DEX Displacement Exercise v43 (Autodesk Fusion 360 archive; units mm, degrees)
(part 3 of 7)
fillet "Fillet91" radius 4.5
extrude "Extrude128" sketch "Plate Cuts" profile of C3 C6 no distance stored from offset 0.5
extrude "Extrude129" sketch "Blister" profile of C8 C9 C11 C12 blind -4.5
mirror "Mirror7"
fillet "Fillet92" radius 1

design "RCT N17 Blister"
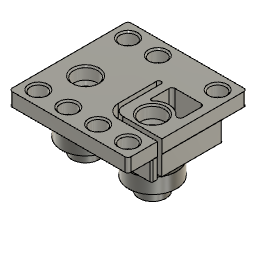
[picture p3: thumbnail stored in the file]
parameter "t_sheet_MAIN" = 6.6 comment "thickness of *most* of the gantry material"
parameter "t_sheet_SECOND" = 6.35 (= "1 / 4 * 1") comment "thickness of the webs"
parameter "od_bearings" = 16
parameter "id_bearings" = 5
parameter "t_bearings" = 5
parameter "p_belt" = 2
parameter "w_belt" = 10
parameter "t_belt" = 1.4
parameter "l_top_belt_to_rail" = 3
parameter "r_cutoutTool" = 2.05 (= "4.1 mm / 2")
parameter "hw_m3_thru" = 3.5
parameter "hw_m3_head" = 5.5
parameter "hw_m3_washer" = 7
parameter "hw_m3_thread" = 2.5
parameter "tab_breather" = 0.2 comment "tab clearance"
parameter "hw_m5_thread" = 4.2
parameter "hw_m5_head" = 8.5
parameter "hw_m5_washer" = 10
parameter "hw_m5_thru" = 5.25
parameter "hw_m6_thru" = 6.5
parameter "hw_m6_head" = 10
parameter "hw_m6_washer" = 12
parameter "l_beltblock" = 15
parameter "hw_plstf6_thread" = 2.94
parameter "hw_plstf6_thru" = 4
parameter "hw_plstf6_head" = 6.86
parameter "hw_plstf6_washer" = 7.92
parameter "hw_m3_flathead" = 6
parameter "hw_m4insert_d" = 6
parameter "hw_m4insert_l" = 4.8
parameter "hw_m4_tappedwj" = 3.3
parameter "hw_m4_thru" = 4.25
parameter "hw_m4_head" = 7
parameter "hw_m4_headheight" = 4
parameter "preload_bearings" = 0.55
parameter "hw_m3insert_d" = 5.4
parameter "hw_m3insert_l" = 3.8
parameter "dist_clearance" = 0.5
parameter "hw_shoulder_headDiameter" = 9
parameter "hw_shoulder_headHeight" = 4
parameter "l_travel" = 405 comment "will be rounded to 10s"
parameter "User Parameter" = 0 (= "min 10")
parameter "nh_rail_width" = "nh_gantry_width - 3"
parameter "l_shoulder_thread" = 10
parameter "hw_n6_thru" = 4.064
parameter "hw_n6_thread" = 3.1
parameter "hw_n6_flathead" = 6.6548
parameter "hw_n6_head" = 6.858
parameter "carriage_offsets" = 0.25
parameter "hw_momentPin_reald" = 3.683
parameter "pinch_by" = 0.2
parameter "d285" = 2
parameter "d344" = 3.5
parameter "d482" = 3.3 (= "t_sheet_MAIN / 2")
parameter "d578" = 0.5
parameter "d683" = 3.683 (= "hw_momentPin_reald")
parameter "d689" = 0.5
parameter "d698" = 5
parameter "d705" = 3.5415 (= "d683 / 2 + 1.7 mm")
parameter "d837" = 0.25
sketch "Plate Cuts" plane through (0, 0, 0) normal (0, 0, 1) x axis (1, 0, 0)
  line L1 (0, 60) -> (0, 0)
  line L2 (3.3, 0) -> (3.3, 60)
  line L3 (-3.3, 60) -> (-3.3, 0)
  line L4 (-15, 10) -> (-5, 10)
  line L5 (-15, 40) -> (-5, 40)
  line L6 (15, 10) -> (5, 10)
  line L7 (-20, 37) -> (-20, 13)
  line L8 (-2, 37) -> (-20, 37)
  line L9 (-2, 43) -> (-2, 37)
  line L10 (12, 43) -> (-2, 43)
  line L11 (12, 37) -> (12, 43)
  line L12 (20.5, 37) -> (12, 37)
  line L13 (20.5, 13) -> (20.5, 37)
  line L14 (-20, 13) -> (20.5, 13)
  circle C1 centre (-5, 10) radius 1.575
  circle C2 centre (-15, 10) radius 1.575
  circle C3 centre (-11.2, 22) radius 8
  circle C4 centre (-15, 40) radius 1.575
  circle C5 centre (-5, 40) radius 1.575
  circle C6 centre (11.2, 22) radius 8
  circle C7 centre (15, 40) radius 1.575
  circle C8 centre (5, 10) radius 1.575
  circle C9 centre (15, 10) radius 1.575
  circle C10 centre (-11.2, 22) radius 8.25
  circle C11 centre (11.2, 22) radius 8.25
  point P1 (0, 0)
  point P2 (0, 0)
  point P3 (0, 60)
  point P7 (-3.3, 60)
  point P4 (3.3, 60)
  point P6 (-3.3, 0)
  point P5 (3.3, 0)
  point P8 (-5, 10)
  point P10 (-5, 10)
  point P9 (-15, 10)
  point P11 (-15, 10)
  point P14 (-15, 40)
  point P15 (-15, 40)
  point P13 (-5, 40)
  point P16 (-5, 40)
  point P12 (-11.2, 22)
  point P17 (11.2, 22)
  point P18 (15, 40)
  point P19 (5, 10)
  point P21 (5, 10)
  point P20 (15, 10)
  point P22 (15, 10)
  point P27 (-2, 37)
  point P25 (-20, 13)
  point P33 (-20, 13)
  coincident P1 P2
  vertical L1
  parallel L1 L2
  parallel L1 L3
  horizontal P3 P7
  horizontal P3 P4
  horizontal P1 P6
  horizontal P1 P5
  coincident P8 P10
  horizontal L4
  coincident P9 P11
  equal C1 C2
  horizontal L5
  coincident P14 P15
  coincident P13 P16
  equal L4 L5
  equal C2 C4
  equal C1 C5
  equal C3 C6
  horizontal P12 P17
  equal C5 C7
  horizontal P16 P18
  horizontal L6
  coincident P19 P21
  coincident P20 P22
  equal C2 C8
  equal C2 C9
  equal L4 L6
  concentric C3 C10
  concentric C6 C11
  vertical L7
  perpendicular L3 L8
  perpendicular L8 L9
  perpendicular L9 L10
  perpendicular L8 L11
  perpendicular L11 L12
  perpendicular L12 L13
  coincident P27 L12
  perpendicular L13 L14
  coincident P25 P33
  dimension "d1151" distance P2 P3 = 60
  dimension "d1152" distance L1 L3 = 3.3 (= "t_sheet_MAIN / 2")
  dimension "d1153" distance L1 L2 = 3.3 (= "d1152")
  dimension "d1154" distance L1 P8 = 5
  dimension "d1156" distance P10 P11 = 10
  dimension "d1157" diameter C2 = 3.15
  dimension "d1158" distance P1 L4 = 10
  dimension "d1159" diameter C3 = 16 (= "od_bearings")
  dimension "d1160" distance P9 L5 = 30
  dimension "d1161" distance L1 P16 = 5
  dimension "d1162" distance L1 P12 = 11.2 (= "od_bearings / 2 + t_sheet_MAIN / 2 - pinch_by / 2")
  dimension "d1163" distance P9 P12 = 12
  dimension "d1164" distance L1 P17 = 11.2 (= "d1162")
  dimension "d1165" distance P16 P18 = 20
  dimension "d1166" distance P1 L6 = 10
  dimension "d1167" distance L1 P21 = 5
  dimension "d1168" distance C6 C11 = 0.25
  dimension "d1169" distance C3 C10 = 0.25 (= "d1168")
  dimension "d1171" distance P16 L9 = 3
  dimension "d1172" distance P16 L8 = 3
  dimension "d1174" distance P16 L10 = 3
  dimension "d1175" distance P18 L11 = 3
  dimension "d1176" distance P18 L13 = 5.5
  dimension "d1177" distance P21 L14 = 3
  dimension "d1229" distance P15 L7 = 5
  dimension "d996" distance = 1.2
  dimension "d997" distance = 5
  dimension "d998" diameter = 24
  dimension "d999" distance = 15
  dimension "d1000" ProfileOffset = 2
  dimension "d1001" AlongDistance = 10
  dimension "d1002" TaperAngle = 0
  dimension "d1004" TaperAngle = 0
  dimension "d1005" ProfileOffset = -0.5
  dimension "d1006" AlongDistance = -55
  dimension "d1007" TaperAngle = 0
  dimension "d467" angle = 5
  dimension "d469" angle = 5
  dimension "d470" angle = 5
  dimension "d471" diameter = 3.5 (= "hw_m3_thru")
  dimension "d472" diameter = 7 (= "hw_m3_washer")
  dimension "d475" distance = 2.4 (= "t_belt + 1 mm")
  dimension "d476" distance = 2.4 (= "d475")
  dimension "d477" distance = 4.477
  dimension "d479" distance = 1
  dimension "d480" distance = 0.75
  dimension "d485" distance = 0.75 (= "d480")
  dimension "d487" diameter = 3.1 (= "hw_n6_thread")
  dimension "d488" diameter = 4.064 (= "hw_n6_thru")
  dimension "d489" Side1Offset = 0.5
  dimension "d490" TaperAngle = 0
  dimension "d491" Side1Offset = 0
  dimension "d492" TaperAngle = 0
  dimension "d493" Side1Offset = 0
  dimension "d494" TaperAngle = 0
  dimension "d495" Side1Offset = 1
  dimension "d496" TaperAngle = 0
  dimension "d497" distance = 9
  dimension "d498" angle = 5 (= "d469")
  dimension "d500" distance = 5
  dimension "d501" radius = 11.075 (= "( 22.15 / 2 ) * 1 mm")
  dimension "d502" Side1Offset = 0
  dimension "d503" TaperAngle = 0
  dimension "d504" diameter = 5.3 (= "hw_m3insert_d - 0.1 mm")
  dimension "d506" diameter = 3.5 (= "hw_m3_thru")
  dimension "d507" Side1Offset = 0
  dimension "d508" TaperAngle = 0
  dimension "d509" AlongDistance = -5
  dimension "d510" TaperAngle = 0
  dimension "d529" AlongDistance = 100
  dimension "d530" TaperAngle = 0
  dimension "d531" countU = 13 (= "nh_gantry_length + 1")
  dimension "d532" CountV = 9 (= "nh_gantry_width + 1")
  dimension "d533" uSpaceDistance = 10
  dimension "d534" vSpaceDistance = -10
  dimension "d535" diameter = 3.3 (= "hw_m4_tappedwj")
  dimension "d541" uSpaceDistance = 10
  dimension "d542" vSpaceDistance = 10
  dimension "d560" distance = 6.6 (= "t_sheet_MAIN")
  dimension "d563" distance = 5 (= "t_bearings")
  dimension "d564" distance = 16 (= "od_bearings")
  dimension "d565" angle = 45 (= "d566")
  dimension "d566" angle = 45
  dimension "d567" distance = 10 (= "l_shoulder_thread")
  dimension "d568" distance = 6.6 (= "t_sheet_MAIN")
  dimension "d569" distance = 45 (= "( ( nh_gantry_width * 10 ) * 1 mm + 10 mm ) / 2")
  dimension "d571" distance = 4.5 (= "hw_shoulder_headHeight + 0.5 mm")
  dimension "d572" distance = 4.5 (= "hw_shoulder_headDiameter / 2")
  dimension "d574" distance = 8.8037
  dimension "d576" distance = 0.5
  dimension "d577" distance = 0.5
  dimension "d580" distance = 0.5
  dimension "d581" distance = 3.5 (= "hw_m4insert_d / 2 + 0.5 mm")
  dimension "d582" distance = 3.5 (= "d581")
  dimension "d583" distance = 2.1
  dimension "d584" distance = 0.8383
  dimension "d586" distance = 1.269 (= "0.5 mm + 0.769 mm")
  dimension "d587" distance = 5
  dimension "d588" distance = 10
  dimension "d589" distance = 5
  dimension "d590" AlongDistance = 65 (= "( nh_gantry_length * 10 + 10 ) / 2 * 1 mm")
  dimension "d591" TaperAngle = 0
  dimension "d597" ProfileOffset = 0.25 (= "carriage_offsets")
  dimension "d599" TaperAngle = 0
  dimension "d601" diameter = 16 (= "od_bearings")
  dimension "d602" diameter = 6 (= "hw_m4insert_d")
  dimension "d603" diameter = 4
  dimension "d604" distance = 0.25
  dimension "d606" AlongDistance = -20
  dimension "d607" TaperAngle = 0
  dimension "d608" ProfileOffset = 0.5
  dimension "d609" AlongDistance = 5 (= "t_bearings")
  dimension "d610" TaperAngle = 0
  dimension "d612" distance = 0.25
  dimension "d613" diameter = 4
  dimension "d614" diameter = 6 (= "hw_m4insert_d")
  dimension "d615" diameter = 16 (= "od_bearings")
  dimension "d616" AlongDistance = -20
  dimension "d617" TaperAngle = 0
  dimension "d618" ProfileOffset = 0.5
  dimension "d619" AlongDistance = 5 (= "t_bearings")
  dimension "d620" TaperAngle = 0
  dimension "d621" AlongDistance = 670 (= "l_actual_complete")
  dimension "d622" TaperAngle = 0
  dimension "d623" distance = 0.1
  dimension "d624" distance = 1.6455
  dimension "d625" distance = 3.4128
  dimension "d626" distance = 13.2 (= "0.5 in + 0.5 mm")
  dimension "d628" distance = 5
  dimension "d630" distance = 30
  dimension "d631" diameter = 4.064 (= "hw_n6_thru")
  dimension "d636" diameter = 6.6548 (= "hw_n6_flathead")
  dimension "d637" diameter = 3.1 (= "hw_n6_thread")
  dimension "d638" distance = 4
  dimension "d639" distance = 4 (= "d638")
  dimension "d641" TaperAngle = 0
  dimension "d642" ProfileOffset = 0
  dimension "d643" Side1Offset = 0
  dimension "d644" TaperAngle = 0
  dimension "d645" ProfileOffset = 0
  dimension "d646" Side1Offset = 0
  dimension "d647" TaperAngle = 0
  dimension "d648" distance = 5
  dimension "d649" distance = 0.75
  dimension "d650" ProfileOffset = 0
  dimension "d651" Side1Offset = 0
  dimension "d652" TaperAngle = 0
  dimension "d653" AlongDistance = 21
  dimension "d654" TaperAngle = 0
  dimension "d655" distance = 1
  dimension "d656" ProfileOffset = 0
  dimension "d657" Side1Offset = 0
  dimension "d658" TaperAngle = 0
  dimension "d659" AlongDistance = 12
  dimension "d660" TaperAngle = 0
  dimension "d661" Side1Offset = 0
  dimension "d662" TaperAngle = 0
  dimension "d667" Radius = 4
  dimension "d669" Radius = 4
  dimension "d670" Radius = 1
  dimension "d673" Radius = 0.5
  dimension "d674" Radius = 0.5
  dimension "d675" Radius = 0.5
  dimension "d676" Radius = 0.5
  dimension "d677" Radius = 0.2
  dimension "d680" distance = 40
  dimension "d681" distance = 6
  dimension "d691" distance = 2.54
  dimension "d692" distance = 0.5 (= "d689")
  dimension "d693" distance = 0.5
  dimension "d696" distance = 0.5
  dimension "d697" distance = 5
  dimension "d701" distance = 1.7
  dimension "d702" distance = 1.7 (= "d701")
  dimension "d706" distance = 2.54 (= "d691")
  dimension "d707" distance = 3.5
  dimension "d708" distance = 0.5
  dimension "d709" ProfileOffset = 0
  dimension "d710" Side1Offset = 0
  dimension "d711" TaperAngle = 0
  dimension "d712" ProfileOffset = 0
  dimension "d713" Side1Offset = 5
  dimension "d714" TaperAngle = 0
  dimension "d715" Side1Offset = 0
  dimension "d716" TaperAngle = 0
  dimension "d717" distance = 0.75
  dimension "d718" distance = 1.7
  dimension "d719" diameter = 16 (= "od_bearings")
  dimension "d720" diameter = 6 (= "hw_m4insert_d")
  dimension "d721" diameter = 4
  dimension "d722" distance = 0.25
  dimension "d723" AlongDistance = -19
  dimension "d724" TaperAngle = 0
  dimension "d725" distance = 1
  dimension "d726" ProfileOffset = 0.5
  dimension "d727" AlongDistance = 5 (= "t_bearings")
  dimension "d728" TaperAngle = 0
  dimension "d729" diameter = 4
  dimension "d730" diameter = 6 (= "hw_m4insert_d")
  dimension "d731" diameter = 16 (= "od_bearings")
  dimension "d732" distance = 1
  dimension "d733" distance = 0.25
  dimension "d734" AlongDistance = -26
  dimension "d735" TaperAngle = 0
  dimension "d736" ProfileOffset = 0.5
  dimension "d737" AlongDistance = 5 (= "t_bearings")
  dimension "d738" TaperAngle = 0
  dimension "d739" distance = 6
  dimension "d740" ProfileOffset = 0
  dimension "d741" Side1Offset = 0
  dimension "d742" TaperAngle = 0
  dimension "d743" Radius = 4
  dimension "d744" distance = -1
  dimension "d745" AlongDistance = 32
  dimension "d746" TaperAngle = 0
  dimension "d747" distance = 0.5
  dimension "d748" distance = 1
  dimension "d749" ProfileOffset = 0
  dimension "d750" AlongDistance = 3
  dimension "d751" TaperAngle = 0
  dimension "d752" ProfileOffset = 0
  dimension "d753" Side1Offset = 0
  dimension "d754" TaperAngle = 0
  dimension "d755" Side1Offset = 0
  dimension "d756" TaperAngle = 0
  dimension "d757" ProfileOffset = 0
  dimension "d758" Side1Offset = 0
  dimension "d759" TaperAngle = 0
  dimension "d760" AlongDistance = 12
  dimension "d761" TaperAngle = 0
  dimension "d762" AlongDistance = -37
  dimension "d763" TaperAngle = 0
  dimension "d764" Side1Offset = 0.5
  dimension "d765" TaperAngle = 0
  dimension "d767" Radius = 3
  dimension "d768" Radius = 2
  dimension "d770" Radius = 3
  dimension "d771" Radius = 3
  dimension "d772" distance = 3
  dimension "d773" distance = 3
  dimension "d774" Radius = 1
  dimension "d775" Radius = 0.5
  dimension "d776" Radius = 2
  dimension "d777" diameter = 5.4 (= "hw_m3insert_d")
  dimension "d778" diameter = 3.5 (= "hw_m3_thru")
  dimension "d779" Side1Offset = 0
  dimension "d780" TaperAngle = 0
  dimension "d781" Side1Offset = 0
  dimension "d782" TaperAngle = 0
  dimension "d783" Radius = 2
  dimension "d784" Radius = 2
  dimension "d785" Radius = 2
  dimension "d786" Radius = 3
  dimension "d788" Radius = 0.5
  dimension "d789" distance = 12
  dimension "d790" distance = 2
  dimension "d791" angle = 45
  dimension "d793" Radius = 2
  dimension "d794" Radius = 2
  dimension "d795" Radius = 1
  dimension "d797" Radius = 2
  dimension "d798" Radius = 1
  dimension "d799" Radius = 2
  dimension "d800" Radius = 4.5
  dimension "d801" distance = 0.275 (= "preload_bearings / 2")
  dimension "d803" distance = -0.5
  dimension "d806" distance = 3
  dimension "d807" AlongDistance = -60
  dimension "d808" distance = 3.8274 (= "d430 / 2")
  dimension "d809" distance = 0.423 (= "1 mm - 0.577 mm")
  dimension "d810" distance = 0.5
  dimension "d813" Side1Offset = 0
  dimension "d814" TaperAngle = 0
  dimension "d815" distance = 0.1
  dimension "d816" distance = 1.75
  dimension "d818" distance = 35
  dimension "d820" distance = 5
  dimension "d821" distance = 5
  dimension "d822" diameter = 4.064 (= "hw_n6_thru")
  dimension "d823" diameter = 6.6548 (= "hw_n6_flathead")
  dimension "d824" distance = 0.6
  dimension "d825" distance = 0.6 (= "d824")
  dimension "d827" TaperAngle = 0
  dimension "d828" diameter = 3.1 (= "hw_n6_thread")
  dimension "d829" Side1Offset = 0
  dimension "d830" TaperAngle = 0
  dimension "d831" distance = 4
  dimension "d832" distance = 4.477 (= "d833")
  dimension "d833" distance = 4.477 (= "d477")
  dimension "d836" diameter = 6.6548 (= "hw_n6_flathead")
  dimension "d839" Side1Offset = 0
  dimension "d840" TaperAngle = 0
  dimension "d841" distance = 0.9
  dimension "d842" angle = 50
  dimension "d843" angle = 50
  dimension "d844" distance = 8
  dimension "d845" distance = 5
  dimension "d846" diameter = 4.5
  dimension "d847" AlongDistance = -7
  dimension "d848" TaperAngle = 0
  dimension "d849" leftDistance = 0.75
  dimension "d850" ProfileOffset = 0
  dimension "d851" Side1Offset = 0
  dimension "d852" TaperAngle = 0
  dimension "d853" ProfileOffset = 0
  dimension "d854" Side1Offset = 0
  dimension "d855" TaperAngle = 0
  dimension "d856" distance = 12.7
  dimension "d857" leftDistance = 1.5
  dimension "d858" distance = 1.5454
  dimension "d859" Radius = 4
  dimension "d860" Radius = 2
  dimension "d861" Radius = 2
  dimension "d862" Radius = 4
  dimension "d863" Radius = 2
  dimension "d864" Radius = 35
  dimension "d865" Radius = 4
  dimension "d866" Radius = 1
  dimension "d869" Side1Offset = 0
  dimension "d870" TaperAngle = 0
  dimension "d872" distance = 1.5
  dimension "d873" leftDistance = 1.5
  dimension "d874" Radius = 2
  dimension "d885" distance = 27.775
  dimension "d886" distance = 30.275 (= "30 mm + preload_bearings / 2")
  dimension "d889" diameter = 3.3 (= "hw_m4_tappedwj")
  dimension "d890" distance = 5
  dimension "d891" distance = 10.275 (= "10 mm + preload_bearings / 2")
  dimension "d893" TaperAngle = 0
  dimension "d894" distance = 17.5
  dimension "d895" distance = 27.5
  dimension "d896" distance = 0.2
  dimension "d897" distance = 0.2 (= "d896")
  dimension "d900" distance = 6
  dimension "d902" distance = 3.7 (= "2 mm + 1.2 mm + 0.5 mm")
  dimension "d903" distance = 1
  dimension "d904" distance = 8
  dimension "d905" distance = 2.54
  dimension "d906" distance = 2.54
  dimension "d907" distance = 2.54
  dimension "d908" Side1Offset = 0
  dimension "d909" TaperAngle = 0
  dimension "d910" ProfileOffset = 0
  dimension "d911" Side1Offset = 0
  dimension "d912" TaperAngle = 0
  dimension "d913" leftDistance = 1.5
  dimension "d915" distance = 5.65
  dimension "d916" distance = 14.65
  dimension "d917" distance = 14.65
  dimension "d918" Side1Offset = 0
  dimension "d919" TaperAngle = 0
  dimension "d920" ChordLen = 4
  dimension "d921" ChordLen = 1
  dimension "d923" distance = 2.54
  dimension "d924" Radius = 2
sketch "Blister" plane through (0, 0, 0) normal (0, 0, 1) x axis (1, 0, 0)
  line L1 (-19.9, 44.9) -> (-19.9, 5.1)
  line L2 (19.9, 44.9) -> (-19.9, 44.9)
  line L3 (19.9, 5.1) -> (19.9, 44.9)
  line L4 (-19.9, 5.1) -> (19.9, 5.1)
  line L5 (3.8, 16.46) -> (3.8, 44.9)
  line L6 (3.3, 0) -> (3.3, 60)
  line L7 (7.44, 33.2818) -> (16.26, 33.2818)
  line L8 (6.44, 26.2818) -> (6.44, 32.2818)
  line L9 (17.26, 32.2818) -> (17.26, 26.2818)
  line L10 (19.9, 16.46) -> (3.8, 16.46)
  line L11 (2.3, 14.96) -> (19.9, 14.96)
  line L12 (2.3, 32.2818) -> (2.3, 14.96)
  line L13 (-1.9, 36.9) -> (-1.9, 42.9)
  line L14 (-19.9, 36.9) -> (-1.9, 36.9)
  line L15 (19.9, 13.1) -> (-19.9, 13.1)
  line L16 (11.9, 42.9) -> (-1.9, 42.9)
  line L17 (11.9, 36.9) -> (11.9, 42.9)
  line L18 (19.9, 36.9) -> (11.9, 36.9)
  line L19 (-3.55, 19.6596) -> (-3.55, 24.3404)
  line L20 (-3.3, 60) -> (-3.3, 0)
  line L21 (19.8, 36.9) -> (19.8, 13.1)
  line L22 (-19.8, 13.1) -> (-19.8, 36.9)
  circle C1 centre (-15, 10) radius 2.7
  circle C2 centre (-5, 10) radius 2.7
  circle C3 centre (5, 10) radius 2.7
  circle C4 centre (15, 10) radius 2.7
  circle C5 centre (15, 40) radius 2.7
  circle C6 centre (-5, 40) radius 2.7
  circle C7 centre (-15, 40) radius 2.7
  circle C8 centre (11.2, 22) radius 4.5
  circle C9 centre (11.2, 22) radius 3
  circle C10 centre (11.2, 22) radius 5.54
  arc A1 centre (6.94, 26.2818) radius 0.5 clockwise from (7.2926, 25.9274) to (6.44, 26.2818)
  arc A2 centre (16.2097, 26.2818) radius 1.0503 clockwise from (17.26, 26.2818) to (15.4114, 25.5994)
  arc A3 centre (7.44, 32.2818) radius 1 clockwise from (6.44, 32.2818) to (7.44, 33.2818)
  arc A4 centre (16.26, 32.2818) radius 1 clockwise from (16.26, 33.2818) to (17.26, 32.2818)
  arc A5 centre (3.05, 32.2818) radius 0.75 clockwise from (2.3, 32.2818) to (3.8, 32.2818)
  circle C11 centre (-11.2, 22) radius 3
  circle C12 centre (-11.2, 22) radius 4.5
  circle C13 centre (-11.2, 22) radius 8
  circle C14 centre (11.2, 22) radius 4
  circle C15 centre (-11.2, 22) radius 4
  point P6 (-15, 10)
  point P8 (-15, 10)
  point P14 (-15, 40)
  point P15 (-15, 40)
  point P13 (-5, 40)
  point P16 (-5, 40)
  point P7 (15, 40)
  point P12 (15, 40)
  point P11 (15, 10)
  point P17 (15, 10)
  point P10 (5, 10)
  point P18 (5, 10)
  point P9 (-5, 10)
  point P19 (-5, 10)
  point P20 (11.2, 22)
  point P21 (11.2, 22)
  point P22 (11.2, 22)
  point P23 (3.8, 44.9)
  point P34 (19.9, 16.46)
  point P35 (7.2926, 25.9274)
  point P30 (6.44, 26.2818)
  point P31 (17.26, 26.2818)
  point P37 (15.4114, 25.5994)
  point P27 (16.26, 33.2818)
  point P40 (16.26, 33.2818)
  point P42 (19.9, 14.96)
  point P45 (3.8, 32.2818)
  point P29 (6.44, 32.2818)
  point P47 (-11.2, 22)
  point P48 (-11.2, 22)
  point P49 (-11.2, 22)
  point P50 (-11.2, 22)
  point P55 (19.9, 13.1)
  point P58 (19.9, 36.9)
  point P52 (-1.9, 36.9)
  point P59 (-3.55, 24.3404)
  point P60 (-3.55, 19.6596)
  point P54 (-19.9, 13.1)
  point P53 (-19.9, 36.9)
  point P63 (19.8, 13.1)
  point P64 (19.8, 36.9)
  point P65 (-19.8, 36.9)
  point P66 (-19.8, 13.1)
  vertical L1
  perpendicular L1 L2
  perpendicular L2 L3
  perpendicular L3 L4
  coincident P6 P8
  equal C1 C7
  equal C1 C2
  equal C1 C3
  equal C1 C4
  equal C1 C6
  equal C1 C5
  coincident P14 P15
  coincident P13 P16
  coincident P7 P12
  coincident P11 P17
  coincident P10 P18
  coincident P9 P19
  coincident P20 P21
  coincident P21 P22
  parallel L3 L5
  coincident L2 P23
  perpendicular L3 L7
  vertical L8
  vertical L9
  concentric C9 C10
  coincident L3 P34
  perpendicular L3 L10
  tangent C10 L10
  tangent L8 A1
  coincident C10 P35
  tangent C10 A1
  horizontal P30 P31
  tangent L9 A2
  coincident C10 P37
  tangent C10 A2
  tangent L8 A3
  tangent L7 A4
  coincident P27 P40
  tangent L9 A4
  tangent L7 A3
  coincident L3 P42
  perpendicular L6 L11
  perpendicular L11 L12
  tangent L5 A5
  tangent L12 A5
  coincident L5 P45
  horizontal P29 P45
  coincident P47 P48
  coincident P47 P49
  coincident P47 P50
  perpendicular L13 L14
  perpendicular L3 L15
  coincident L3 P55
  horizontal L14
  perpendicular L13 L16
  perpendicular L2 L17
  coincident L3 P58
  perpendicular L3 L18
  coincident P52 L18
  coincident C13 P59
  coincident C13 P60
  vertical L19
  coincident L1 P54
  coincident L1 P53
  coincident L15 P63
  coincident L18 P64
  perpendicular L18 L21
  coincident L14 P65
  coincident L15 P66
  perpendicular L15 L22
  concentric C9 C14
  concentric C13 C15
  dimension "d1178" distance L4 P6 = 4.9
  dimension "d1179" distance L1 P6 = 4.9
  dimension "d1180" distance L2 P7 = 4.9
  dimension "d1181" distance L3 P7 = 4.9 (= "d1180")
  dimension "d1182" diameter C1 = 5.4 (= "hw_m3insert_d")
  dimension "d1183" diameter C8 = 9
  dimension "d1184" diameter C9 = 6 (= "hw_m4insert_d")
  dimension "d1185" distance L5 L6 = 0.5
  dimension "d1186" distance L3 L9 = 2.64
  dimension "d1187" distance L5 L8 = 2.64 (= "d1186")
  dimension "d1188" distance P29 P30 = 6
  dimension "d1189" distance C9 C10 = 2.54
  dimension "d1190" radius A1 = 0.5
  dimension "d1191" radius A3 = 1
  dimension "d1192" radius A4 = 1
  dimension "d1193" distance L10 L11 = 1.5 (= "d1194")
  dimension "d1194" distance L5 L12 = 1.5
  dimension "d1198" diameter C12 = 9
  dimension "d1199" diameter C11 = 6 (= "hw_m4insert_d")
  dimension "d1200" diameter C13 = 16 (= "od_bearings")
  dimension "d1201" distance P14 L14 = 3.1
  dimension "d1202" distance P8 L15 = 3.1
  dimension "d1204" distance P13 L13 = 3.1
  dimension "d1205" distance P13 L16 = 2.9
  dimension "d1206" distance P12 L17 = 3.1
  dimension "d1207" distance L19 L20 = 0.25
  dimension "d1230" distance L3 L21 = 0.1
  dimension "d1231" distance L1 L22 = 0.1
  dimension "d1233" distance C9 C14 = 1
  dimension "d1234" distance C11 C15 = 1 (= "d1233")
extrude "Extrude124" new body sketch "Blister" profile of L1 L2 L3 L4 C1 C2 C3 C4 C5 C6 C7 C8 C9 L5 L7 L8 L9 C10 L10 A1 A2 A3 A4 L11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 along normal blind 4.5 (= "hw_m3insert_l + 0.7 mm")
extrude "Extrude125" add sketch "Blister" profile of C8 C9 L5 L7 L8 L9 C10 L10 A1 A2 A3 A4 L11 L12 A5 C11 C12 C13 L13 L14 L15 L16 L17 L18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 no distance stored
extrude "Extrude126" sketch "Blister" profile of C8 C9 C10 C11 C12 C13 L19 blind -0.5
extrude "Extrude127" sketch "Blister" profile of C8 C9 C11 C12 blind -0.5
fillet "Fillet88" radius 0.5
extrude "Extrude130" sketch "Blister" profile of C9 C11 C14 C15 blind 25 from offset 6
chamfer "Chamfer13" distance 1
chamfer "Chamfer12" distance 0.5
fillet "Fillet90" radius 3
fillet "Fillet91" radius 4.5
extrude "Extrude128" sketch "Plate Cuts" profile of C3 C6 no distance stored from offset 0.5
extrude "Extrude129" sketch "Blister" profile of C8 C9 C11 C12 blind -4.5
fillet "Fillet92" radius 1

design "rct-lb-gt3-edge-idler"
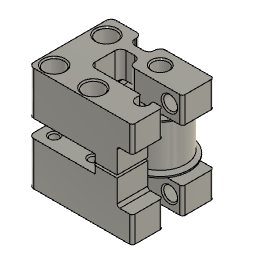
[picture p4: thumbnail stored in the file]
parameter "t_sheet_MAIN" = 6.7 comment "thickness of *most* of the gantry material"
parameter "t_sheet_SECOND" = 6.35 (= "1 / 4 * 1") comment "thickness of the webs"
parameter "od_bearings" = 16
parameter "id_bearings" = 5
parameter "t_bearings" = 5
parameter "p_belt" = 2
parameter "w_belt" = 10
parameter "t_belt" = 1.4
parameter "l_top_belt_to_rail" = 3
parameter "r_cutoutTool" = 2.05 (= "4.1 mm / 2")
parameter "hw_m3_thru" = 3.5
parameter "hw_m3_head" = 5.5
parameter "hw_m3_washer" = 7
parameter "hw_m3_thread" = 2.5
parameter "tab_breather" = 0.2 comment "tab clearance"
parameter "hw_m5_thread" = 4.2
parameter "hw_m5_head" = 8.5
parameter "hw_m5_washer" = 10
parameter "hw_m5_thru" = 5.25
parameter "hw_m6_thru" = 6.5
parameter "hw_m6_head" = 10
parameter "hw_m6_washer" = 12
parameter "l_beltblock" = 15
parameter "hw_plstf6_thread" = 2.94
parameter "hw_plstf6_thru" = 4
parameter "hw_plstf6_head" = 6.86
parameter "hw_plstf6_washer" = 7.92
parameter "hw_m3_flathead" = 6
parameter "hw_m4insert_d" = 6
parameter "hw_m4insert_l" = 4.8
parameter "hw_m4_tappedwj" = 3.3
parameter "hw_m4_thru" = 4.25
parameter "hw_m4_head" = 7
parameter "hw_m4_headheight" = 4
parameter "preload_bearings" = 0.55
parameter "hw_m3insert_d" = 5.3
parameter "hw_m3insert_l" = 3.8
parameter "dist_clearance" = 0.5
parameter "hw_shoulder_headDiameter" = 9
parameter "hw_shoulder_headHeight" = 4
parameter "l_travel" = 405 comment "will be rounded to 10s"
parameter "User Parameter" = 0 (= "min 10")
parameter "nh_rail_width" = "nh_gantry_width - 3"
parameter "l_shoulder_thread" = 10
parameter "hw_n6_thru" = 4.064
parameter "hw_n6_thread" = 3.1
parameter "hw_n6_flathead" = 6.6548
parameter "hw_n6_head" = 6.858
parameter "carriage_offsets" = 0.25
parameter "hw_momentPin_reald" = 3.683
parameter "pinch_by" = 0.2
parameter "d285" = 2
parameter "d344" = 3.5
parameter "d482" = 3.35 (= "t_sheet_MAIN / 2")
parameter "d578" = 0.5
parameter "d683" = 3.683 (= "hw_momentPin_reald")
parameter "d689" = 0.5
parameter "d698" = 5
parameter "d705" = 3.5415 (= "d683 / 2 + 1.7 mm")
parameter "d837" = 0.25
sketch "Sketch35" plane through (0, 0, 0) normal (0, 0, 1) x axis (1, 0, 0)
  line L1 (-0.3, -45) -> (-0.3, 5)
  line L2 (-35.8, 25) -> (-15.3, 25)
  line L3 (-15.3, 5) -> (-15.3, 25)
  line L4 (-0.3, 5) -> (-15.3, 5)
  line L5 (-15.2, 25.1) -> (-25.2, 25.1)
  line L6 (-15.2, 5.1) -> (-15.2, 25.1)
  line L7 (-0.2, 5.1) -> (-15.2, 5.1)
  line L8 (-0.2, -4.9) -> (-0.2, 5.1)
  line L9 (14.5, -4.9) -> (-0.2, -4.9)
  line L10 (14.5, 6.8) -> (14.5, -4.9)
  line L11 (-13.5, 6.8) -> (14.5, 6.8)
  line L12 (-25.2, 26.7) -> (-25.2, 25.1)
  line L13 (-13.5, 26.7) -> (-25.2, 26.7)
  line L14 (-13.5, 26.7) -> (-13.5, 6.8)
  line L15 (-25.2, -4.9) -> (-0.2, -4.9)
  line L16 (-25.2, 25.1) -> (-25.2, -4.9)
  line L17 (-32.45, -45) -> (-32.45, 25)
  line L18 (-35.8, -45) -> (-35.8, 25)
  line L19 (-0.3, -45) -> (-35.8, -45)
  line L20 (-13.5, 21.985) -> (-6, 21.985)
  line L21 (-13.5, 18.615) -> (-6, 18.615)
  line L22 (14.5, 26.3) -> (-6, 26.3)
  line L23 (14.5, 14.3) -> (14.5, 26.3)
  line L24 (-6, 14.3) -> (14.5, 14.3)
  line L25 (-6, 26.3) -> (-6, 14.3)
  line L26 (8.7, -4.9) -> (8.7, 6.8)
  circle C1 centre (0, 20.3) radius 9.7
  circle C2 centre (0, 20.3) radius 8
  circle C3 centre (0, 20.3) radius 3
  circle C4 centre (0, 20.3) radius 4.5
  circle C5 centre (-5.3, 0) radius 2.65
  circle C6 centre (-20.3, 0) radius 2.65
  circle C7 centre (3.8, 0) radius 2.65
  circle C8 centre (-20.3, 20) radius 2.65
  circle C9 centre (-20.3, 20) radius 1.575
  circle C10 centre (-20.3, 0) radius 1.575
  circle C11 centre (-5.3, 0) radius 1.575
  circle C12 centre (8.5, 5.05) radius 2.5
  circle C13 centre (-20.3, 20) radius 3.75
  circle C14 centre (-20.3, 0) radius 3.75
  circle C15 centre (-5.3, 0) radius 3.75
  point P1 (0, 0)
  point P3 (0, 20.3)
  point P5 (0, 20.3)
  point P8 (9.7, 20.3)
  point P11 (0, 30)
  point P6 (-0.3, 5)
  point P13 (-0.3, 5)
  point P24 (-13.5, 26.7)
  point P25 (-13.5, 26.7)
  point P15 (-25.2, 25.1)
  point P27 (-25.2, 25.1)
  point P28 (-32.45, 25)
  point P7 (-0.3, -45)
  point P31 (-0.3, -45)
  point P29 (-32.45, -45)
  point P14 (-13.5, 6.8)
  point P22 (-13.5, 6.8)
  point P32 (-5.3, 0)
  point P34 (3.8, 0)
  point P36 (-13.5, 21.985)
  point P38 (-13.5, 18.615)
  point P35 (-6, 21.985)
  point P37 (-6, 18.615)
  point P33 (-20.3, 0)
  point P43 (-20.3, 20)
  point P41 (14.5, 14.3)
  point P48 (4.5, 20.3)
  point P49 (8.7, 6.8)
  point P50 (8.7, -4.9)
  point P45 (-20.3, 0)
  point P53 (-5.3, 0)
  point P4 (0, 20.3)
  point P47 (8.5, 5.05)
  point P52 (-20.3, 0)
  point P51 (-20.3, 20)
  concentric C1 C2
  vertical P1 P3
  concentric C1 C3
  concentric C1 C4
  horizontal P5 P8
  coincident C1 P11
  vertical P5 P11
  vertical L1
  coincident C1 P8
  perpendicular L2 L3
  perpendicular L3 L4
  coincident P6 P13
  perpendicular L3 L5
  perpendicular L5 L6
  perpendicular L6 L7
  perpendicular L5 L8
  perpendicular L8 L9
  perpendicular L9 L10
  perpendicular L10 L11
  perpendicular L5 L12
  perpendicular L12 L13
  vertical L14
  coincident P24 P25
  perpendicular L1 L15
  perpendicular L9 L16
  coincident P15 P27
  coincident L2 P28
  perpendicular L2 L17
  perpendicular L2 L18
  perpendicular L17 L19
  coincident P7 P31
  coincident P29 L19
  coincident P14 P22
  horizontal P32 P34
  equal C5 C7
  coincident L14 P36
  perpendicular L14 L20
  coincident L14 P38
  perpendicular L14 L21
  horizontal L22
  vertical L23
  horizontal L24
  vertical L25
  coincident P35 L25
  coincident P37 L25
  equal C6 C8
  vertical P33 P43
  concentric C8 C9
  concentric C6 C10
  concentric C5 C11
  equal C10 C11
  equal C9 C11
  coincident L10 P41
  coincident C4 P48
  horizontal P3 P48
  coincident L11 P49
  coincident L9 P50
  perpendicular L9 L26
  concentric C8 C13
  concentric C6 C14
  concentric C5 C15
  equal C14 C15
  equal C13 C15
  equal C5 C6
  horizontal P45 P53
  horizontal P1 P34
  dimension "d1327" diameter C1 = 19.4 (= "16 mm + ( 2 * 1.7 ) * 1 mm")
  dimension "d1328" diameter C2 = 16 (= "od_bearings")
  dimension "d1329" diameter C3 = 6 (= "hw_m4insert_d")
  dimension "d1330" diameter C4 = 9
  dimension "d1331" distance L1 P8 = 10
  dimension "d1332" distance L2 P11 = 5
  dimension "d1337" distance L3 L6 = 0.1
  dimension "d1338" distance L4 L7 = 0.1 (= "d1337")
  dimension "d1339" distance L1 L8 = 0.1 (= "d1337")
  dimension "d1340" distance L2 L5 = 0.1 (= "d1337")
  dimension "d1342" distance P6 P7 = 50
  dimension "d1348" distance P7 L18 = 35.5
  dimension "d1349" distance L17 L18 = 3.35 (= "t_sheet_MAIN / 2")
  dimension "d1351" distance L1 P32 = 5
  dimension "d1353" diameter C5 = 5.3 (= "hw_m3insert_d")
  dimension "d1355" distance L7 L11 = 1.7
  dimension "d1356" distance L6 L14 = 1.7
  dimension "d1359" distance P4 L21 = 1.685 (= "( 3.37 / 2 ) * 1 mm")
  dimension "d1360" distance P3 L20 = 1.685 (= "d1359")
  dimension "d1361" distance P3 L22 = 6
  dimension "d1362" distance P3 L24 = 6 (= "d1361")
  dimension "d1363" distance P5 L25 = 6 (= "d1361")
  dimension "d1377" distance P33 P43 = 20
  dimension "d1378" diameter C11 = 3.15
  dimension "d1379" distance L1 P34 = 4.1
  dimension "d1380" diameter C12 = 5
  dimension "d1381" distance L23 P47 = 6
  dimension "d1382" distance L11 P47 = 1.75
  dimension "d1398" distance L23 P48 = 10
  dimension "d1399" distance P8 L26 = 1
  dimension "d1407" distance L2 L13 = 1.7
  dimension "d1413" diameter C15 = 7.5
  dimension "d1449" distance L4 P32 = 5
  dimension "d1450" distance P32 P52 = 15
  dimension "d1452" distance L2 P43 = 5
  dimension "d1453" distance L16 P43 = 4.9
  dimension "d1454" distance L15 P33 = 4.9
  dimension "d1455" distance L3 P51 = 5
  dimension "d1456" = 24.9
  dimension "d531" countU = 13 (= "nh_gantry_length + 1")
  dimension "d532" CountV = 9 (= "nh_gantry_width + 1")
  dimension "d533" uSpaceDistance = 10
  dimension "d534" vSpaceDistance = -10
  dimension "d535" diameter = 3.3 (= "hw_m4_tappedwj")
  dimension "d541" uSpaceDistance = 10
  dimension "d542" vSpaceDistance = 10
  dimension "d560" distance = 6.6 (= "t_sheet_MAIN")
  dimension "d563" distance = 5 (= "t_bearings")
  dimension "d564" distance = 16 (= "od_bearings")
  dimension "d565" angle = 45 (= "d566")
  dimension "d566" angle = 45
  dimension "d567" distance = 10 (= "l_shoulder_thread")
  dimension "d568" distance = 6.6 (= "t_sheet_MAIN")
  dimension "d569" distance = 45 (= "( ( nh_gantry_width * 10 ) * 1 mm + 10 mm ) / 2")
  dimension "d571" distance = 4.5 (= "hw_shoulder_headHeight + 0.5 mm")
  dimension "d572" distance = 4.5 (= "hw_shoulder_headDiameter / 2")
  dimension "d574" distance = 8.8037
  dimension "d576" distance = 0.5
  dimension "d577" distance = 0.5
  dimension "d580" distance = 0.5
  dimension "d581" distance = 3.5 (= "hw_m4insert_d / 2 + 0.5 mm")
  dimension "d582" distance = 3.5 (= "d581")
  dimension "d583" distance = 2.1
  dimension "d584" distance = 0.8383
  dimension "d586" distance = 1.269 (= "0.5 mm + 0.769 mm")
  dimension "d587" distance = 5
  dimension "d588" distance = 10
  dimension "d589" distance = 5
  dimension "d590" AlongDistance = 65 (= "( nh_gantry_length * 10 + 10 ) / 2 * 1 mm")
  dimension "d591" TaperAngle = 0
  dimension "d597" ProfileOffset = 0.25 (= "carriage_offsets")
  dimension "d599" TaperAngle = 0
  dimension "d601" diameter = 16 (= "od_bearings")
  dimension "d602" diameter = 6 (= "hw_m4insert_d")
  dimension "d603" diameter = 4
  dimension "d604" distance = 0.25
  dimension "d606" AlongDistance = -20
  dimension "d607" TaperAngle = 0
  dimension "d608" ProfileOffset = 0.5
  dimension "d609" AlongDistance = 5 (= "t_bearings")
  dimension "d610" TaperAngle = 0
  dimension "d612" distance = 0.25
  dimension "d613" diameter = 4
  dimension "d614" diameter = 6 (= "hw_m4insert_d")
  dimension "d615" diameter = 16 (= "od_bearings")
  dimension "d616" AlongDistance = -20
  dimension "d617" TaperAngle = 0
  dimension "d618" ProfileOffset = 0.5
  dimension "d619" AlongDistance = 5 (= "t_bearings")
  dimension "d620" TaperAngle = 0
  dimension "d621" AlongDistance = 670 (= "l_actual_complete")
  dimension "d622" TaperAngle = 0
  dimension "d623" distance = 0.1
  dimension "d624" distance = 1.6455
  dimension "d625" distance = 3.4128
  dimension "d626" distance = 13.2 (= "0.5 in + 0.5 mm")
  dimension "d628" distance = 5
  dimension "d630" distance = 30
  dimension "d631" diameter = 4.064 (= "hw_n6_thru")
  dimension "d636" diameter = 6.6548 (= "hw_n6_flathead")
  dimension "d637" diameter = 3.1 (= "hw_n6_thread")
  dimension "d638" distance = 4
  dimension "d639" distance = 4 (= "d638")
  dimension "d641" TaperAngle = 0
  dimension "d642" ProfileOffset = 0
  dimension "d643" Side1Offset = 0
  dimension "d644" TaperAngle = 0
  dimension "d645" ProfileOffset = 0
  dimension "d646" Side1Offset = 0
  dimension "d647" TaperAngle = 0
  dimension "d648" distance = 5
  dimension "d649" distance = 0.75
  dimension "d650" ProfileOffset = 0
  dimension "d651" Side1Offset = 0
  dimension "d652" TaperAngle = 0
  dimension "d653" AlongDistance = 21
  dimension "d654" TaperAngle = 0
  dimension "d655" distance = 1
  dimension "d656" ProfileOffset = 0
  dimension "d657" Side1Offset = 0
  dimension "d658" TaperAngle = 0
  dimension "d659" AlongDistance = 12
  dimension "d660" TaperAngle = 0
  dimension "d661" Side1Offset = 0
  dimension "d662" TaperAngle = 0
  dimension "d667" Radius = 4
  dimension "d669" Radius = 4
  dimension "d670" Radius = 1
  dimension "d673" Radius = 0.5
  dimension "d674" Radius = 0.5
  dimension "d675" Radius = 0.5
  dimension "d676" Radius = 0.5
  dimension "d677" Radius = 0.2
  dimension "d680" distance = 40
  dimension "d681" distance = 6
  dimension "d691" distance = 2.54
  dimension "d692" distance = 0.5 (= "d689")
  dimension "d693" distance = 0.5
  dimension "d696" distance = 0.5
  dimension "d697" distance = 5
  dimension "d701" distance = 1.7
  dimension "d702" distance = 1.7 (= "d701")
  dimension "d706" distance = 2.54 (= "d691")
  dimension "d707" distance = 3.5
  dimension "d708" distance = 0.5
  dimension "d709" ProfileOffset = 0
  dimension "d710" Side1Offset = 0
  dimension "d711" TaperAngle = 0
  dimension "d712" ProfileOffset = 0
  dimension "d713" Side1Offset = 5
  dimension "d714" TaperAngle = 0
  dimension "d715" Side1Offset = 0
  dimension "d716" TaperAngle = 0
  dimension "d717" distance = 0.75
  dimension "d718" distance = 1.7
  dimension "d719" diameter = 16 (= "od_bearings")
  dimension "d720" diameter = 6 (= "hw_m4insert_d")
  dimension "d721" diameter = 4
  dimension "d722" distance = 0.25
  dimension "d723" AlongDistance = -19
  dimension "d724" TaperAngle = 0
  dimension "d725" distance = 1
  dimension "d726" ProfileOffset = 0.5
  dimension "d727" AlongDistance = 5 (= "t_bearings")
  dimension "d728" TaperAngle = 0
  dimension "d729" diameter = 4
  dimension "d730" diameter = 6 (= "hw_m4insert_d")
  dimension "d731" diameter = 16 (= "od_bearings")
  dimension "d732" distance = 1
  dimension "d733" distance = 0.25
  dimension "d734" AlongDistance = -26
  dimension "d735" TaperAngle = 0
  dimension "d736" ProfileOffset = 0.5
  dimension "d737" AlongDistance = 5 (= "t_bearings")
  dimension "d738" TaperAngle = 0
  dimension "d739" distance = 6
  dimension "d740" ProfileOffset = 0
  dimension "d741" Side1Offset = 0
  dimension "d742" TaperAngle = 0
  dimension "d743" Radius = 4
  dimension "d744" distance = -1
  dimension "d745" AlongDistance = 32
  dimension "d746" TaperAngle = 0
  dimension "d747" distance = 0.5
  dimension "d748" distance = 1
  dimension "d749" ProfileOffset = 0
  dimension "d750" AlongDistance = 3
  dimension "d751" TaperAngle = 0
  dimension "d752" ProfileOffset = 0
  dimension "d753" Side1Offset = 0
  dimension "d754" TaperAngle = 0
  dimension "d755" Side1Offset = 0
  dimension "d756" TaperAngle = 0
  dimension "d757" ProfileOffset = 0
  dimension "d758" Side1Offset = 0
  dimension "d759" TaperAngle = 0
  dimension "d760" AlongDistance = 12
  dimension "d761" TaperAngle = 0
  dimension "d762" AlongDistance = -37
  dimension "d763" TaperAngle = 0
  dimension "d764" Side1Offset = 0.5
  dimension "d765" TaperAngle = 0
  dimension "d767" Radius = 3
  dimension "d768" Radius = 2
  dimension "d770" Radius = 3
  dimension "d771" Radius = 3
  dimension "d772" distance = 3
  dimension "d773" distance = 3
  dimension "d774" Radius = 1
  dimension "d775" Radius = 0.5
  dimension "d776" Radius = 2
  dimension "d777" diameter = 5.4 (= "hw_m3insert_d")
  dimension "d778" diameter = 3.5 (= "hw_m3_thru")
  dimension "d779" Side1Offset = 0
  dimension "d780" TaperAngle = 0
  dimension "d781" Side1Offset = 0
  dimension "d782" TaperAngle = 0
  dimension "d783" Radius = 2
  dimension "d784" Radius = 2
  dimension "d785" Radius = 2
  dimension "d786" Radius = 3
  dimension "d788" Radius = 0.5
  dimension "d789" distance = 12
  dimension "d790" distance = 2
  dimension "d791" angle = 45
  dimension "d793" Radius = 2
  dimension "d794" Radius = 2
  dimension "d795" Radius = 1
  dimension "d797" Radius = 2
  dimension "d798" Radius = 1
  dimension "d799" Radius = 2
  dimension "d800" Radius = 4.5
  dimension "d801" distance = 0.275 (= "preload_bearings / 2")
  dimension "d803" distance = -0.5
  dimension "d806" distance = 3
  dimension "d807" AlongDistance = -60
  dimension "d808" distance = 3.8274 (= "d430 / 2")
  dimension "d809" distance = 0.423 (= "1 mm - 0.577 mm")
  dimension "d810" distance = 0.5
  dimension "d813" Side1Offset = 0
  dimension "d814" TaperAngle = 0
  dimension "d815" distance = 0.1
  dimension "d816" distance = 1.75
  dimension "d818" distance = 35
  dimension "d820" distance = 5
  dimension "d821" distance = 5
  dimension "d822" diameter = 4.064 (= "hw_n6_thru")
  dimension "d823" diameter = 6.6548 (= "hw_n6_flathead")
  dimension "d824" distance = 0.6
  dimension "d825" distance = 0.6 (= "d824")
  dimension "d827" TaperAngle = 0
  dimension "d828" diameter = 3.1 (= "hw_n6_thread")
  dimension "d829" Side1Offset = 0
  dimension "d830" TaperAngle = 0
  dimension "d831" distance = 4
  dimension "d832" distance = 4.477 (= "d833")
  dimension "d833" distance = 4.477 (= "d477")
  dimension "d836" diameter = 6.6548 (= "hw_n6_flathead")
  dimension "d839" Side1Offset = 0
  dimension "d840" TaperAngle = 0
  dimension "d841" distance = 0.9
  dimension "d842" angle = 50
  dimension "d843" angle = 50
  dimension "d844" distance = 8
  dimension "d845" distance = 5
  dimension "d846" diameter = 4.5
  dimension "d847" AlongDistance = -7
  dimension "d848" TaperAngle = 0
  dimension "d849" leftDistance = 0.75
  dimension "d850" ProfileOffset = 0
  dimension "d851" Side1Offset = 0
  dimension "d852" TaperAngle = 0
  dimension "d853" ProfileOffset = 0
  dimension "d854" Side1Offset = 0
  dimension "d855" TaperAngle = 0
  dimension "d856" distance = 12.7
  dimension "d857" leftDistance = 1.5
  dimension "d858" distance = 1.5454
  dimension "d859" Radius = 4
  dimension "d860" Radius = 2
  dimension "d861" Radius = 2
  dimension "d862" Radius = 4
  dimension "d863" Radius = 2
  dimension "d864" Radius = 35
  dimension "d865" Radius = 4
  dimension "d866" Radius = 1
  dimension "d869" Side1Offset = 0
  dimension "d870" TaperAngle = 0
  dimension "d872" distance = 1.5
  dimension "d873" leftDistance = 1.5
  dimension "d874" Radius = 2
  dimension "d885" distance = 27.775
  dimension "d886" distance = 30.275 (= "30 mm + preload_bearings / 2")
  dimension "d889" diameter = 3.3 (= "hw_m4_tappedwj")
  dimension "d890" distance = 5
  dimension "d891" distance = 10.275 (= "10 mm + preload_bearings / 2")
  dimension "d893" TaperAngle = 0
  dimension "d894" distance = 17.5
  dimension "d895" distance = 27.5
  dimension "d896" distance = 0.2
  dimension "d897" distance = 0.2 (= "d896")
  dimension "d900" distance = 6
  dimension "d902" distance = 3.7 (= "2 mm + 1.2 mm + 0.5 mm")
  dimension "d903" distance = 1
  dimension "d904" distance = 8
  dimension "d905" distance = 2.54
  dimension "d906" distance = 2.54
  dimension "d907" distance = 2.54
  dimension "d908" Side1Offset = 0
  dimension "d909" TaperAngle = 0
  dimension "d910" ProfileOffset = 0
  dimension "d911" Side1Offset = 0
  dimension "d912" TaperAngle = 0
  dimension "d913" leftDistance = 1.5
  dimension "d915" distance = 5.65
  dimension "d916" distance = 14.65
  dimension "d917" distance = 14.65
  dimension "d918" Side1Offset = 0
  dimension "d919" TaperAngle = 0
  dimension "d920" ChordLen = 4
  dimension "d921" ChordLen = 1
  dimension "d923" distance = 2.54
  dimension "d924" Radius = 2
extrude "Extrude141" new body sketch "Sketch35" profile of C3 C4 L14 L20 L21 L22 L23 L24 L25 blind -10 from offset -10
extrude "Extrude142" cut sketch "Sketch35" profile of C3 no distance stored
extrude "Extrude143" add sketch "Sketch35" profile of L5 L6 L7 L8 L9 L10 L11 L12 L13 L14 C7 to an object from offset -0.5
extrude "Extrude144" add sketch "Sketch35" profile of L1 L2 L3 L4 L5 L6 L7 L8 L15 L16 C5 C6 to an object from offset -3.35 (= "-t_sheet_MAIN / 2")
fillet "Fillet98" radius 2.1
fillet "Fillet99" radius 2
extrude "Extrude145" sketch "Sketch35" profile of L11 C12 L26 blind 9
chamfer "Chamfer23" distance 1
fillet "Fillet100" radius 0.5
sketch "Sketch36" plane through (0, 26.3, 0) normal (0, 1, 0) x axis (-1, 0, 0)
  line L1 (3.9, -10) -> (3.9, -20)
  line L2 (-14.5, -10) -> (3.9, -10)
  line L3 (-14.5, -20) -> (-14.5, -10)
  line L4 (3.9, -20) -> (-14.5, -20)
  line L5 (-14.5, -15) -> (-9.5, -15)
  circle C1 centre (-9.5, -15) radius 2.65
  circle C2 centre (-9.5, -15) radius 3.65
  point P6 (-9.5, -15)
  point P7 (-9.5, -15)
  point P8 (-14.5, -15)
  point P9 (-9.5, -15)
  coincident P6 P7
  midpoint L3 P8
  perpendicular L3 L5
  coincident P7 P9
  dimension "d1388" diameter C1 = 5.3 (= "hw_m3insert_d")
  dimension "d1389" distance P7 P8 = 5
  dimension "d1393" distance C1 C2 = 1
extrude "Extrude146" cut sketch "Sketch36" profile of C1 to an object
extrude "Extrude147" sketch "Sketch36" profile of C1 C2 to an object from offset 9
chamfer "Chamfer24" distance 1
extrude "Extrude148" cut sketch "Sketch35" profile of L9 L10 L11 C12 L26 to an object
fillet "Fillet101" radius 1
chamfer "Chamfer25" distance 0.5
chamfer "Chamfer26" distance 0.5
fillet "Fillet102" radius 1
fillet "Fillet103" radius 2
fillet "Fillet104" radius 2
fillet "Fillet105" radius 1
fillet "Fillet106" radius 0.5
fillet "Fillet107" radius 2
chamfer "Chamfer37" distance 1
mirror "Mirror10"
extrude "Extrude149" cut sketch "Sketch35" profile of C9 C10 C11 no distance stored
extrude "Extrude150" sketch "Sketch35" profile of C3 C4 blind 4
chamfer "Chamfer27" distance 0.25
extrude "Extrude151" cut sketch "Sketch35" profile of C5 C6 C8 C9 C10 C11 no distance stored from offset -10
extrude "Extrude152" sketch "Sketch35" profile of C5 C6 C8 C13 C14 C15 no distance stored from offset 4
extrude "Extrude153" cut sketch "Sketch35" profile of C5 C6 C8 C9 C10 C11 C13 C14 C15 no distance stored from offset 10
chamfer "Chamfer28" distance 2.175
chamfer "Chamfer29" distance 1
chamfer "Chamfer30" distance 0.5
chamfer "Chamfer31" distance 0.5
sketch "Sketch37" plane through (0, 0, 0) normal (0, 0, 1) x axis (1, 0, 0)
  circle C1 centre (0, 20.3) radius 8
  circle C2 centre (0, 20.3) radius 6.3
  circle C3 centre (0, 20.3) radius 9.7
  circle C4 centre (0, 20.3) radius 11.2
  point P2 (0, 20.3)
  point P3 (0, 20.3)
  point P4 (0, 20.3)
  coincident P2 P3
  coincident P3 P4
  concentric C1 C3
  concentric C2 C4
  dimension "d1430" diameter C1 = 16 (= "od_bearings")
  dimension "d1431" distance C1 C2 = 1.7
  dimension "d1432" distance C1 C3 = 1.7
  dimension "d1433" distance C3 C4 = 1.5
extrude "Extrude154" new body sketch "Sketch37" profile of C1 C2 along normal blind 5 (= "9.5 mm - t_bearings + 0.5 mm")
extrude "Extrude155" add sketch "Sketch37" profile of C1 C3 along normal blind 9.5
extrude "Extrude156" add sketch "Sketch37" profile of C3 C4 blind -0.5 from offset 9.5
chamfer "Chamfer32" distance 1.7
chamfer "Chamfer33" distance 1 distance 1.5
chamfer "Chamfer34" distance 0.5
mirror "Mirror11"
combine "Combine22"
chamfer "Chamfer35" distance 0.5
chamfer "Chamfer36" distance 0.5
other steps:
step "Mirror"

design "rct-dex-hearth" references "rct-lb-gt2-stray-idler"
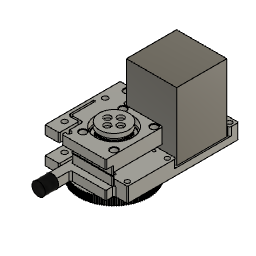
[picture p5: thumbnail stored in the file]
parameter "t_sheet_MAIN" = 6.7 comment "thickness of *most* of the gantry material"
parameter "t_sheet_SECOND" = 6.35 (= "1 / 4 * 1") comment "thickness of the webs"
parameter "od_bearings" = 16
parameter "id_bearings" = 5
parameter "t_bearings" = 5
parameter "r_cutoutTool" = 2.05 (= "4.1 mm / 2")
parameter "hw_m3_thru" = 3.5
parameter "hw_m3_head" = 5.5
parameter "hw_m3_washer" = 7
parameter "hw_m3_thread" = 2.5
parameter "hw_m5_thread" = 4.2
parameter "hw_m5_head" = 8.5
parameter "hw_m5_washer" = 10
parameter "hw_m5_thru" = 5.25
parameter "hw_m6_thru" = 6.5
parameter "hw_m6_head" = 10
parameter "hw_m6_washer" = 12
parameter "l_beltblock" = 15
parameter "hw_plstf6_thread" = 2.94
parameter "hw_plstf6_thru" = 4
parameter "hw_plstf6_head" = 6.86
parameter "hw_plstf6_washer" = 7.92
parameter "hw_m3_flathead" = 6
parameter "hw_m4insert_d" = 6
parameter "hw_m4insert_l" = 4.8
parameter "hw_m4_tappedwj" = 3.3
parameter "hw_m4_thru" = 4.25
parameter "hw_m4_head" = 7
parameter "hw_m4_headheight" = 4
parameter "hw_m3insert_d" = 5.4
parameter "hw_m3insert_l" = 3.8
parameter "dist_clearance" = 0.5
parameter "hw_shoulder_headDiameter" = 9
parameter "hw_shoulder_headHeight" = 4
parameter "l_travel" = 405 comment "will be rounded to 10s"
parameter "User Parameter" = 0 (= "min 10")
parameter "l_shoulder_thread" = 10
parameter "pinch_by" = 0.2
parameter "pd_maindrive" = 26.738 (= "( nt_maindrive * 3 / PI ) * 1 mm")
parameter "pd_pinion" = 12.7324 (= "( nt_pinion * 2 / PI ) * 1 mm")
parameter "pd_drive" = 78.9409 (= "( nt_drive * 2 / PI ) * 1 mm")
parameter "c_dist_manuel" = 59
parameter "midler_x" = 39.5
parameter "midler_y" = 18
parameter "d285" = 2
parameter "d344" = 3.5
parameter "d482" = 3.35 (= "t_sheet_MAIN / 2")
parameter "d578" = 0.5
parameter "d689" = 0.5
parameter "d698" = 5
parameter "d837" = 0.25
parameter "d1845" = 6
